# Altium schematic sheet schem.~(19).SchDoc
size A; SheetNumber: 1; SheetTotal: 1
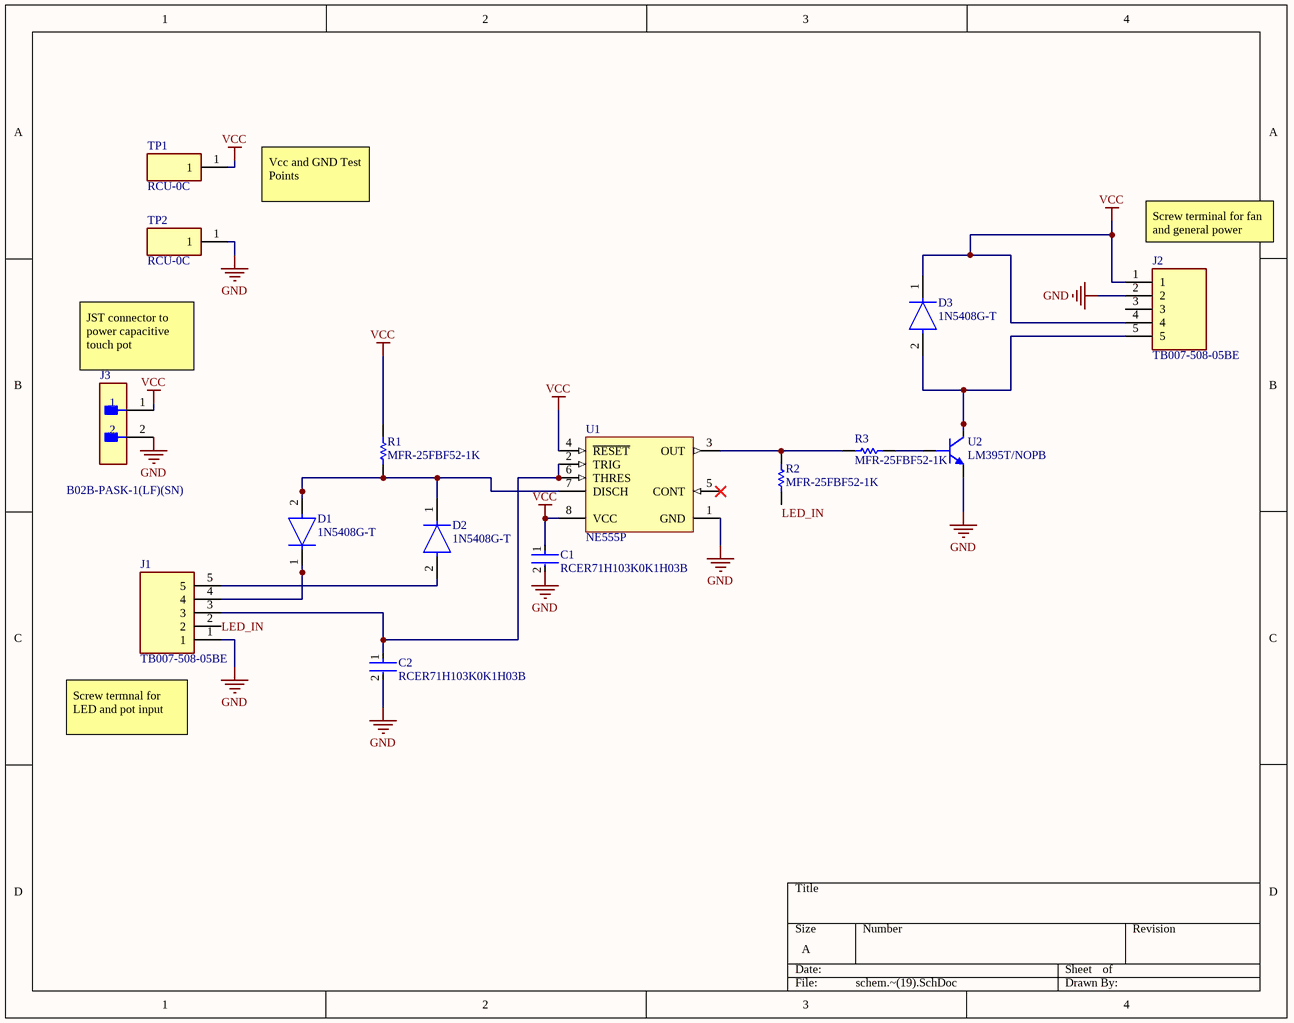
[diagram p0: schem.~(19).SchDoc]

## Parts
C1  RCER71H103K0K1H03B  [FP-RCE0K1-MFG]
C2  RCER71H103K0K1H03B  [FP-RCE0K1-MFG]
D1  1N5408G-T  [FP-DO-201AD-MFG]
D2  1N5408G-T  [FP-DO-201AD-MFG]
D3  1N5408G-T  [FP-DO-201AD-MFG]
J1  TB007-508-05BE  [CUI_TB007-508-05BE]
J2  TB007-508-05BE  [CUI_TB007-508-05BE]
J3  B02B-PASK-1(LF)(SN)  [FP-B02B-PASK-1_LF_SN-MFG]
R1  MFR-25FBF52-1K  [RESA60-630X240]
R2  MFR-25FBF52-1K  [RESA60-630X240]
R3  MFR-25FBF52-1K  [RESA60-630X240]
TP1  RCU-0C  [TP+195X110]
TP2  RCU-0C  [TP+195X110]
U1  NE555P  [P0008A]
U2  LM395T/NOPB  [NDE0003A]

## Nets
GND: C1.2 C2.2 J1.1 J2.2 J3.2 TP2.1 U1.1(GND) U2.2(E)
VCC: C1.1 D3.1(C) J2.1 J2.4 J3.1 R1.2 TP1.1 U1.4(~{RESET}) U1.8(VCC)
LED_IN: J1.2 R2.1
NetC2_1: C2.1 J1.3 U1.2(TRIG) U1.6(THRES)
NetD1_1: D1.1(C) J1.4
NetD1_2: D1.2(A) D2.1(C) R1.1 U1.7(DISCH)
NetD2_2: D2.2(A) J1.5
NetD3_2: D3.2(A) J2.5 U2.3(C)
NetR2_2: R2.2 R3.2 U1.3(OUT)
NetR3_1: R3.1 U2.1(B)

Not connected (* = marked no-connect by the designer): J2 3; U1 5(CONT)*

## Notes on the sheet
- Vcc and GND Test Points
- (near J2) Screw terminal for fan and general power
- JST connector to power capacitive touch pot
- (near J1) Screw termnal for LED and pot input

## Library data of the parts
C1 C2 = CMP-06035-044411-1: Cap Ceramic 10nF 50V X7R ±10% Radial 5mm +125°C Automotive Bulk; Lead/Base Style: Formed Leads; Lead Diameter: 0.5mm
D1-D3 = CMP-12791-000058-1: DIODE GEN PURP 1KV 3A DO201AD; Element Configuration: Single; Polarity: Standard; Max Reverse Current: 5uA; Reverse Recovery Time: 2us; Max Surge Current: 125A; Forward Voltage: 1.1V; Capacitance: 40pF
J3 = CMP-17439-000415-1: CONN HEADER VERT 2POS 2MM; Number of Contacts: 2; Current Rating: 3A; Insulation Resistance: 1GR; Mated Stacking Heights: 14.9mm; Voltage Rating: 250V; Gender: Male
R1-R3 = CMP-1659-00075-1: Axial Resistor, 1 KOhm, +/- 1%, 250 mW, -55 to 155 degC, 2-Pin THD, RoHS, Bulk; Voltage Rating: 250 V; Resistance: 10 kohm; Power Rating: 250 mW
TP1 TP2 = RCU-0C: Natural PC Test Point - - Plating Surface Mount Mounting Type; MF: TE Connectivity AMP Connectors
U1 = CMP-2000-04954-1: Precision Timer, 4.5 to 16 V, 0 to 70 degC, 8-Pin DIP, Pb-Free, Tube; Manufacturer: TexasInstruments; Maximum High Level Output Current: -200mA; Number of Internal Timers: 1; Operating Supply Voltage: 5; Maximum Low Level Output Current: 200mA; Rad Hard: No
U2 = CMP-0063-01416-3: Ultra Reliable Power Transistor, 3-pin TO-220, Pb-Free; Manufacturer: Texas Instruments; PowerWise: N; PackageTopMarking: NSUZXYTTE#*LM395T; CompType: MiscPower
